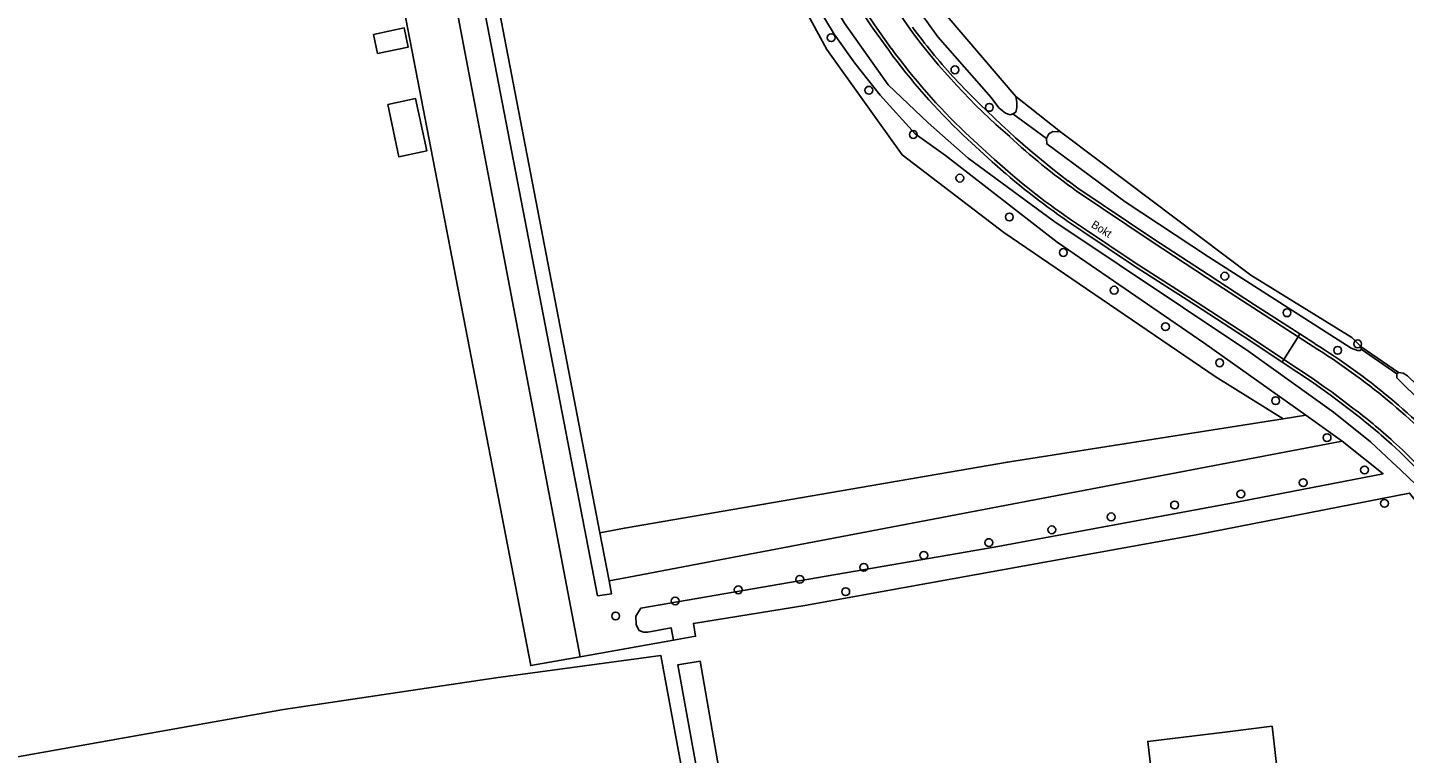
# Model space of a CAD drawing. Extents: x 162515 to 163909, y 388494 to 389773.
# Drawn here: x 163081.8 to 163253.8, y 389330.6 to 389421.2 of the extents above; entities that cross this region are included whole.
import ezdxf

# ---------------------------------------------------------------- set-up
doc = ezdxf.new("R2010")
doc.units = 0
for name, color, linetype in [('IMGEO_Boom', 7, 'Continuous'), ('IMGEO_Boomteelt', 7, 'Continuous'), ('IMGEO_Duiker', 7, 'Continuous'), ('IMGEO_Grasland_overig', 7, 'Continuous'), ('IMGEO_Hek', 7, 'Continuous'), ('IMGEO_Loofbos', 7, 'Continuous'), ('IMGEO_Openbare_ruimte_label', 7, 'Continuous'), ('IMGEO_Pand', 7, 'Continuous'), ('IMGEO_Rijbaan_lokaal_gesloten', 7, 'Continuous'), ('IMGEO_Rijbaan_lokaal_halfverhard', 7, 'Continuous'), ('IMGEO_Waterloop', 7, 'Continuous')]:
    doc.layers.add(name, color=color, linetype=linetype)

msp = doc.modelspace()

# ---------------------------------------------------------------- linework, layer by layer
at = {"layer": 'IMGEO_Boom'}
for centre in [(163182.23, 389419.93), (163197.69, 389415.92), (163186.94, 389413.37), (163201.99, 389411.23), (163192.49, 389407.84), (163198.3, 389402.4), (163204.49, 389397.55), (163211.23, 389393.11), (163231.4, 389390.16), (163217.58, 389388.4), (163239.17, 389385.59), (163223.99, 389383.85), (163248, 389381.7), (163245.51, 389380.89), (163230.76, 389379.34), (163237.76, 389374.61), (163244.18, 389370), (163248.86, 389365.96), (163241.2, 389364.38), (163233.41, 389362.96), (163225.13, 389361.59), (163251.35, 389361.79), (163217.21, 389360.1), (163209.79, 389358.49), (163201.93, 389356.89), (163186.31, 389353.8), (163193.8, 389355.3), (163178.31, 389352.3), (163170.62, 389351), (163184.05, 389350.76), (163162.74, 389349.6), (163155.31, 389347.72)]:
    msp.add_circle(centre, 0.489, dxfattribs=at)
at = {"layer": 'IMGEO_Boomteelt'}
msp.add_lwpolyline([(163060.88, 389326.63), (163113.83, 389336.05), (163140.33, 389340.02), (163160.97, 389342.79), (163195.3, 389156.75)], dxfattribs=at)
at = {"layer": 'IMGEO_Duiker'}
msp.add_lwpolyline([(163248.43, 389381.03), (163252.89, 389377.96)], dxfattribs=at)
at = {"layer": 'IMGEO_Grasland_overig'}
for points in [[(163130.44, 389477.03), (163132.04, 389477.85), (163133.75, 389478.83), (163137.19, 389482.57), (163144.19, 389483.83), (163149.18, 389484.42), (163151.22, 389484.22), (163152.11, 389483.42), (163152.6, 389482.56), (163152.85, 389481.8), (163163.76, 389452.65), (163166.02, 389447.32), (163181.67, 389418.44), (163191.08, 389405.29), (163203.79, 389395.63), (163230.21, 389377.63), (163238.68, 389372.36)], [(163210.88, 389408.18), (163205.28, 389412.58)], [(163209.11, 389407.35), (163204.93, 389410.41)], [(163248.42, 389381.33), (163253.12, 389378.12)], [(163252.89, 389377.96), (163248.43, 389381.03)], [(163162.52, 389344.71), (163150.89, 389342.64)]]:
    msp.add_lwpolyline(points, dxfattribs=at)
at = {"layer": 'IMGEO_Hek'}
for points in [[(163162.52, 389344.71), (163150.89, 389342.64)], [(163165.3, 389345.2), (163162.52, 389344.71)], [(163144.7, 389341.54), (163150.89, 389342.64)]]:
    msp.add_lwpolyline(points, dxfattribs=at)
at = {"layer": 'IMGEO_Loofbos'}
for points in [[(163150.89, 389342.64), (163125.49, 389475.87), (163125.15, 389475.81)], [(163150.89, 389342.64), (163144.7, 389341.54), (163119.52, 389471.84)], [(163153.34, 389358.11), (163156.41, 389358.71), (163204.24, 389366.94), (163238.68, 389372.36)], [(163238.68, 389372.36), (163241.51, 389372.81)], [(163154.49, 389352.12), (163157.64, 389352.72), (163246.08, 389369.56)]]:
    msp.add_lwpolyline(points, dxfattribs=at)
at = {"layer": 'IMGEO_Pand'}
for points in [[(163125.06, 389420.35), (163128.9, 389421.15), (163129.4, 389418.76), (163125.56, 389417.96), (163125.06, 389420.35)], [(163126.84, 389411.6), (163130.32, 389412.34), (163131.7, 389405.79), (163128.21, 389405.06), (163126.84, 389411.6)], [(163237.3, 389333.96), (163237.92, 389328.84), (163232.34, 389328.17), (163222.39, 389326.96), (163221.77, 389332.07), (163231.72, 389333.28), (163237.3, 389333.96)]]:
    msp.add_lwpolyline(points, dxfattribs=at)
at = {"layer": 'IMGEO_Rijbaan_lokaal_gesloten'}
for points in [[(163182.61, 389429.39), (163185.2, 389425.26), (163187.66, 389421.52), (163189.74, 389418.59)], [(163199, 389408.05), (163202.63, 389404.74), (163204.3, 389403.25)], [(163240.55, 389382.6), (163234.89, 389386.24), (163229.12, 389390.01), (163222.32, 389394.46), (163212.83, 389400.82)], [(163213.89, 389396.06), (163220.21, 389391.84), (163227.97, 389386.86), (163234.87, 389382.36), (163238.79, 389379.76)], [(163238.79, 389379.76), (163240.55, 389382.6)], [(163240.55, 389382.6), (163242.44, 389381.39)], [(163247.24, 389373.81), (163244.8, 389375.66), (163243.71, 389376.42), (163242.46, 389377.32), (163238.79, 389379.76)], [(163255.38, 389366.68), (163253.61, 389368.48), (163252.49, 389369.47)]]:
    msp.add_lwpolyline(points, dxfattribs=at)
for centre, radius, start, end in [((163350.56, 389529.93), 192.3, 208.3482, 214.5001), ((163258.57, 389470.17), 82.69, 216.4795, 229.1912), ((163254.22, 389465.89), 79.96, 216.2625, 226.3283), ((163262.81, 389470.68), 85.9, 227.2682, 234.4143), ((163266.33, 389475.91), 95.54, 229.5111, 236.7071), ((163197.98, 389310.01), 84.09, 42.4194, 58.0866), ((163202.8, 389314.74), 73.93, 47.7649, 53.0481)]:
    msp.add_arc(centre, radius, start, end, dxfattribs=at)
at = {"layer": 'IMGEO_Rijbaan_lokaal_halfverhard'}
for points in [[(163189.42, 389418.36), (163187.33, 389421.29), (163184.87, 389425.04), (163182.27, 389429.18)], [(163204.04, 389402.95), (163202.36, 389404.44), (163198.73, 389407.76)], [(163211.84, 389402.04), (163213.05, 389401.15), (163222.54, 389394.79), (163229.33, 389390.35), (163235.11, 389386.58), (163240.77, 389382.94)], [(163238.57, 389379.42), (163234.65, 389382.03), (163227.76, 389386.53), (163219.99, 389391.51), (163213.66, 389395.72)], [(163240.77, 389382.94), (163240.55, 389382.6)], [(163242.65, 389381.73), (163240.77, 389382.94)], [(163238.79, 389379.76), (163238.57, 389379.42)], [(163238.57, 389379.42), (163242.24, 389376.99), (163244.56, 389375.34), (163247, 389373.49)], [(163252.22, 389369.17), (163253.32, 389368.2), (163255.1, 389366.39)]]:
    msp.add_lwpolyline(points, dxfattribs=at)
for centre, radius, start, end in [((163254.37, 389466.74), 76.88, 216.2816, 222.2161), ((163254.19, 389465.87), 80.33, 216.2634, 226.34), ((163283.57, 389495.71), 117.99, 223.1077, 232.5563), ((163266.36, 389475.96), 95.99, 229.5121, 236.7024), ((163198.01, 389310.03), 84.46, 42.4232, 58.088), ((163202.5, 389314.38), 73.99, 47.7817, 53.0315)]:
    msp.add_arc(centre, radius, start, end, dxfattribs=at)
at = {"layer": 'IMGEO_Waterloop'}
for points in [[(163152.49, 389487.83), (163153.39, 389487.38), (163154.08, 389487.04), (163155.98, 389485.49), (163159.33, 389474.91), (163161.39, 389469.3), (163169.31, 389449.78), (163173.5, 389440.5), (163178.57, 389430.66), (163183.89, 389421.75), (163189.35, 389414.03), (163194.35, 389409.29), (163199.34, 389404.88), (163210.06, 389397.04), (163234.4, 389380.75), (163244.97, 389373.16), (163249.61, 389369.49), (163252.27, 389366.97), (163253.38, 389365.92), (163256.21, 389363.24)], [(163241.51, 389372.81), (163228.8, 389381.84), (163210.45, 389394.39), (163196.52, 389405.21), (163192.71, 389407.91), (163188.34, 389412.77), (163185.17, 389416.76), (163182.61, 389420.39), (163179.11, 389426.18), (163175.68, 389432.23), (163173.11, 389437.23), (163166.24, 389452.1), (163162.68, 389461.14), (163156.77, 389477.34), (163155.26, 389482.1), (163154.61, 389484.12), (163154.16, 389485.01), (163152.04, 389486.12)], [(163130.2, 389478.28), (163128.35, 389478.1), (163153.04, 389350.25), (163154.8, 389350.51), (163154.49, 389352.12)], [(163153.34, 389358.11), (163130.44, 389477.03)], [(163204.93, 389410.41), (163204.59, 389410.29), (163203.99, 389410.5), (163203.18, 389411.19), (163202.2, 389412.47), (163195.54, 389420.02), (163191.5, 389425.69), (163186.14, 389434.53), (163183.37, 389439.55), (163179.12, 389447.77), (163170.32, 389468.84), (163170.4, 389469.6), (163170.64, 389469.9)], [(163205.28, 389412.58), (163196.7, 389422.61), (163188.63, 389434.29), (163181.58, 389448.15), (163175.47, 389462.53), (163172.68, 389469.73)], [(163205.28, 389412.58), (163205.42, 389411.89), (163205.41, 389411.22), (163205.29, 389410.64), (163204.93, 389410.41)], [(163210.88, 389408.18), (163209.91, 389408.2), (163209.42, 389407.91), (163209.11, 389407.35)], [(163248.42, 389381.33), (163247.27, 389382.49), (163234.64, 389390.29), (163215.73, 389404.52), (163210.88, 389408.18)], [(163248.43, 389381.03), (163248.37, 389380.88), (163247.96, 389380.86), (163247.18, 389381.17), (163229.37, 389392.56), (163218.97, 389399.45), (163209.16, 389406.67), (163209.11, 389407.35)], [(163248.43, 389381.03), (163248.42, 389381.33)], [(163259.93, 389371.34), (163259.25, 389371.16), (163252.89, 389377.46), (163252.89, 389377.96)], [(163253.12, 389378.12), (163252.89, 389377.96)], [(163253.12, 389378.12), (163253.68, 389378.06), (163254.23, 389377.73), (163256.62, 389375.41)], [(163241.51, 389372.81), (163246.08, 389369.56)], [(163246.08, 389369.56), (163251.18, 389365.49), (163232.25, 389361.83), (163202.61, 389356.33), (163158.46, 389348.72), (163157.84, 389347.71), (163157.88, 389346.64), (163158.26, 389345.91), (163158.79, 389345.7), (163159.32, 389345.69), (163162.24, 389346.25), (163162.52, 389344.71)], [(163272.84, 389329.15), (163269.92, 389337.34), (163267.21, 389343.16), (163260.26, 389355.43), (163257.5, 389359.27), (163254.48, 389363.08), (163227.82, 389357.88), (163178.93, 389349.02), (163165.02, 389346.81), (163165.3, 389345.2), (163162.52, 389344.71)], [(163154.49, 389352.12), (163153.34, 389358.11)], [(163196.6, 389156.9), (163179.71, 389250), (163163.08, 389341.65), (163165.85, 389342.07), (163171.58, 389309.29), (163181.6, 389251.97), (163181.95, 389250), (163198.32, 389157.1)]]:
    msp.add_lwpolyline(points, dxfattribs=at)

# ---------------------------------------------------------------- texts
at = {"layer": 'IMGEO_Openbare_ruimte_label'}
msp.add_text('Bokt', height=1, rotation=327.5816, dxfattribs=at).set_placement((163214.62, 389396.34))

doc.saveas('drawing.dxf')
